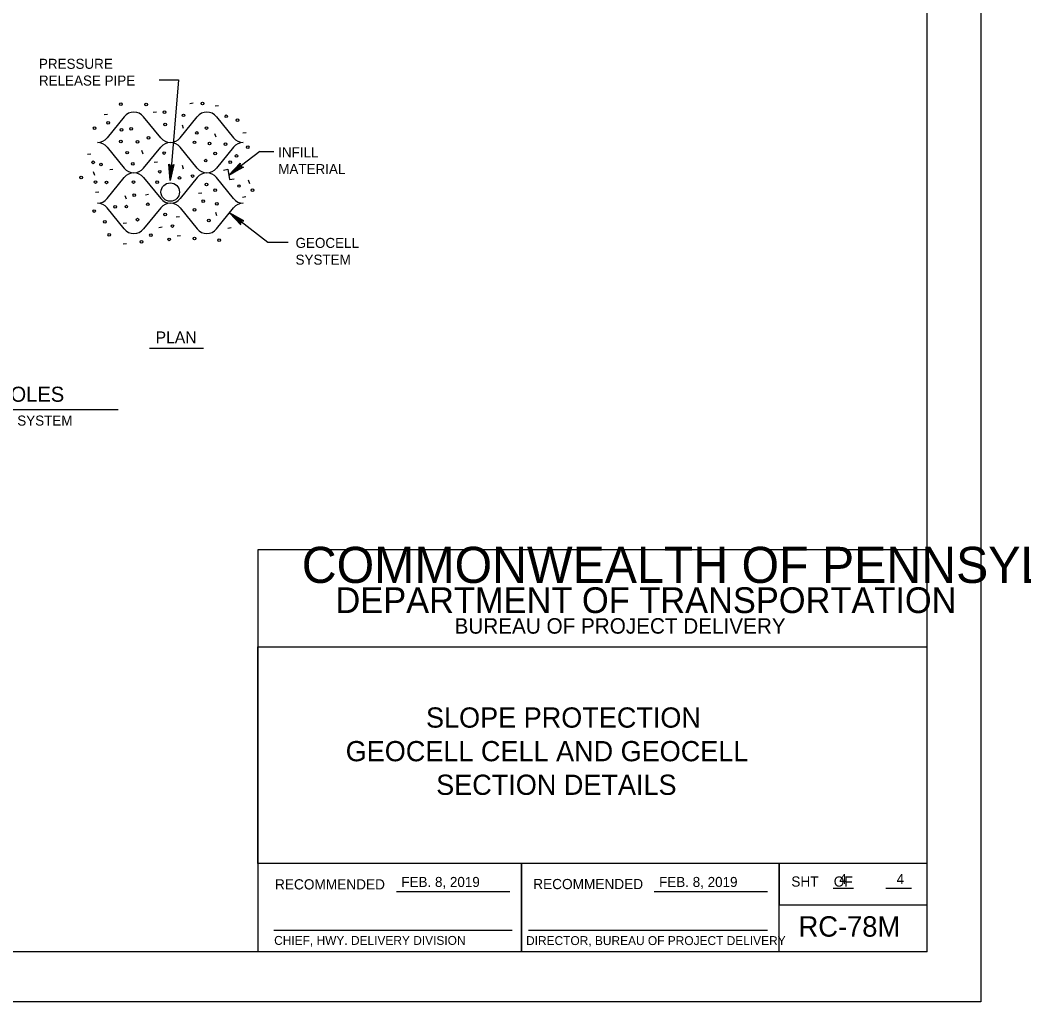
# Model space of a CAD drawing. Extents: x 638850 to 644908, y 297188 to 298900.
# Drawn here: x 640245.4 to 640545.3, y 297459.5 to 297752.8 of the extents above; entities that cross this region are included whole.
import ezdxf

# ---------------------------------------------------------------- set-up
doc = ezdxf.new("R2010")
doc.units = 0
for name, color, linetype in [('1', 7, 'Continuous'), ('2', 7, 'Continuous'), ('3', 7, 'Continuous'), ('9', 7, 'Continuous'), ('PLT-BNDY', 7, 'Continuous')]:
    doc.layers.add(name, color=color, linetype=linetype)

msp = doc.modelspace()

# ---------------------------------------------------------------- linework, layer by layer
at = {"layer": '1'}
for p, q in [((640516.44, 297474.53), (640516.44, 298038.53)), ((640292.75, 297734.91), (640290.23, 297704.9)), ((640297.11, 297727.92), (640296.13, 297727.79)), ((640304.69, 297727.21), (640303.71, 297727.08)), ((640271.51, 297724.6), (640270.53, 297724.47)), ((640286.21, 297725.27), (640285.23, 297725.15)), ((640293.83, 297721.5), (640294.16, 297720.47)), ((640303.55, 297718.89), (640303.88, 297717.86)), ((640312.98, 297719.15), (640312.01, 297719.02)), ((640266.54, 297712.75), (640265.56, 297712.62)), ((640281.74, 297713.91), (640282.08, 297712.88)), ((640317.05, 297713.57), (640307.82, 297706.5)), ((640286.44, 297710.37), (640285.46, 297710.25)), ((640293.83, 297709.41), (640294.16, 297708.37)), ((640267.29, 297707.51), (640267.62, 297706.48)), ((640273.18, 297708.2), (640272.2, 297708.07)), ((640313.62, 297705.02), (640313.95, 297703.99)), ((640268.91, 297701.36), (640267.93, 297701.24)), ((640276.77, 297700.4), (640277.1, 297699.36)), ((640283.84, 297700.65), (640282.86, 297700.53)), ((640299.72, 297701.09), (640298.74, 297700.96)), ((640312.87, 297699.94), (640311.89, 297699.81)), ((640293.08, 297694.01), (640292.1, 297693.89)), ((640303.78, 297695.42), (640304.12, 297694.38)), ((640319.45, 297686.3), (640308, 297695.17)), ((640277.2, 297692.12), (640276.22, 297691.99)), ((640287.87, 297690.89), (640286.89, 297690.77)), ((640308.48, 297690.69), (640307.5, 297690.57)), ((640293.31, 297688.32), (640292.34, 297688.2)), ((640277.2, 297685.95), (640276.22, 297685.82)), ((640516.44, 297594.53), (640316.44, 297594.53)), ((640316.44, 297594.53), (640316.44, 297474.53)), ((640516.44, 297565.57), (640516.44, 297594.53)), ((640316.44, 297500.89), (640316.44, 297565.57)), ((640316.44, 297565.57), (640516.44, 297565.57)), ((640516.44, 297500.89), (640316.44, 297500.89)), ((640395.24, 297474.53), (640395.24, 297500.89)), ((640395.24, 297500.89), (640395.24, 297474.53)), ((640472.24, 297474.53), (640472.24, 297500.89)), ((640472.24, 297500.89), (640472.24, 297488.57)), ((640516.44, 297474.53), (640516.44, 297500.89)), ((640488.3, 297493.5), (640494.45, 297493.5)), ((640504.11, 297493.5), (640511.76, 297493.5)), ((640357.9, 297492.52), (640391.79, 297492.52)), ((640434.9, 297492.52), (640468.77, 297492.52)), ((640472.24, 297488.57), (640516.44, 297488.57)), ((640321.2, 297480.96), (640392.45, 297480.96)), ((640397.37, 297480.96), (640468.71, 297480.96)), ((640516.44, 297474.53), (639730.44, 297474.53))]:
    msp.add_line(p, q, dxfattribs=at)
for points in [[(640291.19, 297709.44), (640290.85, 297709.3), (640290.23, 297704.9), (640291.19, 297709.44), (640291.41, 297709.66), (640290.23, 297704.9), (640290.38, 297709.34), (640290.07, 297709.53), (640290.23, 297704.9), (640289.87, 297709.79), (640290.07, 297709.53)], [(640311.84, 297708.84), (640311.5, 297709.01), (640307.82, 297706.5), (640311.84, 297708.84), (640312.15, 297708.83), (640307.82, 297706.5), (640311.21, 297709.37), (640311.14, 297709.73), (640307.82, 297706.5), (640311.2, 297710.06), (640311.14, 297709.73)], [(640306.24, 297707.93), (640307.54, 297708.23), (640308.02, 297705.21), (640309.35, 297705.41)], [(640312, 297692.81), (640311.66, 297692.65), (640308, 297695.17), (640312, 297692.81), (640312.31, 297692.82), (640308, 297695.17), (640311.38, 297692.28), (640311.3, 297691.92), (640308, 297695.17), (640311.36, 297691.59), (640311.3, 297691.92)]]:
    msp.add_lwpolyline(points, dxfattribs=at)
for centre, radius in [((640275.52, 297727.65), 0.391), ((640283.11, 297727.6), 0.402), ((640299.93, 297727.84), 0.402), ((640288.56, 297725.27), 0.391), ((640294.24, 297724.33), 0.391), ((640307.04, 297724.04), 0.402), ((640267.7, 297720.49), 0.402), ((640271.73, 297722.1), 0.402), ((640278.6, 297720.3), 0.391), ((640288.79, 297721.62), 0.402), ((640301.12, 297720.53), 0.391), ((640310.36, 297722.9), 0.391), ((640275.76, 297720.01), 0.402), ((640283.82, 297717.64), 0.402), ((640298.27, 297719.06), 0.402), ((640275.52, 297716.5), 0.391), ((640280.5, 297716.41), 0.402), ((640297.56, 297716.26), 0.391), ((640302.06, 297715.93), 0.402), ((640306.8, 297715.7), 0.402), ((640313.44, 297714.84), 0.391), ((640277.42, 297713.18), 0.391), ((640288.44, 297713.06), 0.391), ((640303.72, 297712.9), 0.402), ((640310.12, 297712.19), 0.402), ((640267.23, 297710.29), 0.402), ((640269.6, 297709.63), 0.391), ((640279.08, 297709.82), 0.402), ((640300.88, 297710.81), 0.391), ((640308.23, 297710.36), 0.402), ((640263.67, 297705.78), 0.402), ((640287.14, 297707.49), 0.391), ((640293.06, 297705.62), 0.402), ((640296.97, 297706.19), 0.391), ((640267.94, 297704.41), 0.391), ((640271.26, 297704.31), 0.402), ((640279.31, 297704.41), 0.391), ((640286.42, 297704.36), 0.402), ((640301.12, 297703.7), 0.391), ((640310.83, 297703.22), 0.391), ((640279.55, 297700.52), 0.402), ((640303.72, 297701.99), 0.402), ((640314.86, 297701.99), 0.402), ((640273.86, 297697.01), 0.402), ((640277.18, 297697.06), 0.391), ((640283.58, 297697.77), 0.391), ((640300.17, 297698.72), 0.391), ((640304.2, 297697.91), 0.402), ((640267.58, 297695.75), 0.391), ((640288.79, 297694.69), 0.391), ((640297.56, 297696.11), 0.391), ((640270.78, 297692.51), 0.402), ((640280.5, 297693.17), 0.402), ((640290.93, 297691.27), 0.402), ((640301.83, 297692.93), 0.402), ((640272.09, 297688.66), 0.402), ((640284.53, 297688.52), 0.391), ((640289.98, 297687.29), 0.402), ((640297.56, 297687.57), 0.391), ((640281.68, 297686.58), 0.402), ((640304.91, 297687.05), 0.402)]:
    msp.add_circle(centre, radius, dxfattribs=at)
at = {"layer": '2'}
for p, q in [((640276.55, 297723.92), (640271.45, 297717.61)), ((640287.44, 297717.61), (640282.34, 297723.92)), ((640293.23, 297717.61), (640298.32, 297723.92)), ((640304.11, 297723.92), (640309.21, 297717.61)), ((640271.45, 297714.84), (640276.55, 297708.53)), ((640282.34, 297708.53), (640287.44, 297714.84)), ((640298.32, 297708.53), (640293.23, 297714.84)), ((640309.21, 297714.84), (640304.11, 297708.53)), ((640271.45, 297699.46), (640276.55, 297705.77)), ((640282.34, 297705.77), (640287.44, 297699.46)), ((640298.32, 297705.77), (640293.23, 297699.46)), ((640309.21, 297699.46), (640304.11, 297705.77)), ((640276.55, 297690.39), (640271.45, 297696.7)), ((640287.44, 297696.7), (640282.34, 297690.39)), ((640293.23, 297696.7), (640298.32, 297690.39)), ((640304.11, 297690.39), (640309.21, 297696.7))]:
    msp.add_line(p, q, dxfattribs=at)
for centre, start, end in [((640279.45, 297721.58), 90, 141.0518), ((640279.45, 297721.58), 38.9482, 90), ((640301.22, 297721.58), 90, 141.0518), ((640301.22, 297721.58), 38.9482, 90), ((640268.56, 297719.95), 270, 321.0518), ((640268.56, 297712.5), 38.9482, 90), ((640290.33, 297719.95), 218.9482, 270), ((640290.33, 297712.5), 90, 141.0518), ((640290.33, 297719.95), 270, 321.0518), ((640290.33, 297712.5), 38.9482, 90), ((640312.11, 297719.95), 218.9482, 270), ((640312.11, 297712.5), 90, 141.0518), ((640279.45, 297710.87), 218.9482, 270), ((640279.45, 297703.43), 90, 141.0518), ((640279.45, 297710.87), 270, 321.0518), ((640279.45, 297703.43), 38.9482, 90), ((640301.22, 297710.87), 218.9482, 270), ((640301.22, 297703.43), 90, 141.0518), ((640301.22, 297710.87), 270, 321.0518), ((640301.22, 297703.43), 38.9482, 90), ((640268.56, 297701.8), 270, 321.0518), ((640268.56, 297694.36), 38.9482, 90), ((640290.33, 297701.8), 218.9482, 270), ((640290.33, 297694.36), 90, 141.0518), ((640290.33, 297701.8), 270, 321.0518), ((640290.33, 297694.36), 38.9482, 90), ((640312.11, 297701.8), 218.9482, 270), ((640312.11, 297694.36), 90, 141.0518), ((640279.45, 297692.73), 218.9482, 270), ((640279.45, 297692.73), 270, 321.0518), ((640301.22, 297692.73), 218.9482, 270), ((640301.22, 297692.73), 270, 321.0518)]:
    msp.add_arc(centre, 3.72, start, end, dxfattribs=at)
at = {"layer": '3'}
for p, q in [((640284.09, 297654.76), (640300.2, 297654.76)), ((640178.84, 297636.49), (640274.71, 297636.49))]:
    msp.add_line(p, q, dxfattribs=at)
msp.add_circle((640290.29, 297701.41), 2.76, dxfattribs=at)
at = {"layer": '9'}
for p, q in [((640286.94, 297734.91), (640292.75, 297734.91)), ((640317.05, 297713.57), (640321.19, 297713.57)), ((640325.51, 297686.3), (640319.45, 297686.3))]:
    msp.add_line(p, q, dxfattribs=at)
at = {"layer": 'PLT-BNDY'}
msp.add_lwpolyline([(639691.44, 298053.53), (640532.44, 298053.53), (640532.44, 297459.53), (639691.44, 297459.53)], close=True, dxfattribs=at)

# ---------------------------------------------------------------- texts
at = {"layer": '1'}
for s, height, p in [('COMMONWEALTH OF PENNSYLVANIA', 10.7834, (640329.59, 297584.67)), ('DEPARTMENT OF TRANSPORTATION', 7.6843, (640339.65, 297575.68)), ('BUREAU OF PROJECT DELIVERY', 4.6221, (640375.23, 297569.52)), ('SLOPE PROTECTION', 6.04, (640366.7, 297541.45)), ('GEOCELL CELL AND GEOCELL', 6.04, (640342.71, 297531.41)), ('SECTION DETAILS', 6.04, (640369.74, 297521.37)), ('RECOMMENDED', 3.048, (640321.6, 297493.12)), ('FEB. 8, 2019', 3, (640359.35, 297493.86)), ('RECOMMENDED', 3.048, (640398.73, 297493.21)), ('FEB. 8, 2019', 3, (640436.35, 297493.86)), ('SHT    OF', 3.048, (640475.84, 297493.96)), ('4', 3.05, (640490.16, 297494.7)), ('4', 3.05, (640507.29, 297494.7)), ('APPROVED', 0.0192, (640359.46, 297492.46)), ('RC-78M', 6.096, (640478.01, 297479.02)), ('CHIEF, HWY. DELIVERY DIVISION', 2.6623, (640321.34, 297476.57)), ('DIRECTOR, BUREAU OF PROJECT DELIVERY', 2.6623, (640396.6, 297476.51))]:
    msp.add_text(s, height=height, dxfattribs=at).set_placement(p)
at = {"layer": '3'}
for s, height, p in [('PRESSURE', 3, (640251.06, 297738.22)), ('RELEASE PIPE', 3, (640251.06, 297733.22)), ('INFILL', 3, (640322.55, 297711.78)), ('MATERIAL', 3, (640322.55, 297706.78)), ('GEOCELL', 3, (640327.73, 297684.73)), ('SYSTEM', 3, (640327.73, 297679.73)), ('PLAN', 3.5, (640285.93, 297656.28)), ('PRESSURE RELIEF HOLES', 4.5, (640180.7, 297638.78)), ('DRAINAGE THROUGH GEOCELL SYSTEM', 3, (640181.06, 297631.66))]:
    msp.add_text(s, height=height, dxfattribs=at).set_placement(p)

doc.saveas('drawing.dxf')
